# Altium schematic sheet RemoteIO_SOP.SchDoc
size 431 x 279 mm; Date: Not shown in title block; ApprovedBy: Not shown in title block; CheckedBy: Not shown in title block; Author: Not shown in title block; CompanyName: Not shown in title block; Engineer: Not shown in title block; Organization: Not shown in title block; Address1: Not shown in title block; Address2: Not shown in title block; Address3: Not shown in title block; Address4: Not shown in title block; DocumentNumber: 8; Revision: Use project parameter SCH_Rev; SheetNumber: 8; SheetTotal: 14; PageSetup: Record=PageOptions¦CenterHorizontal=True¦CenterVertical=True¦PrintScale=1.00¦XCorrection=1.00¦YCorrection=1.00¦PrintKind=0¦BorderSize=5000000¦LeftOffset=0¦BottomOffset=0¦Orientation=2¦PaperLength=1000¦PaperWidth=1000¦Scale=100¦PaperSource=15¦PrintQuality=600¦MediaType=1¦DitherType=10¦PaperKind=Letter¦PrintScaleMode=1
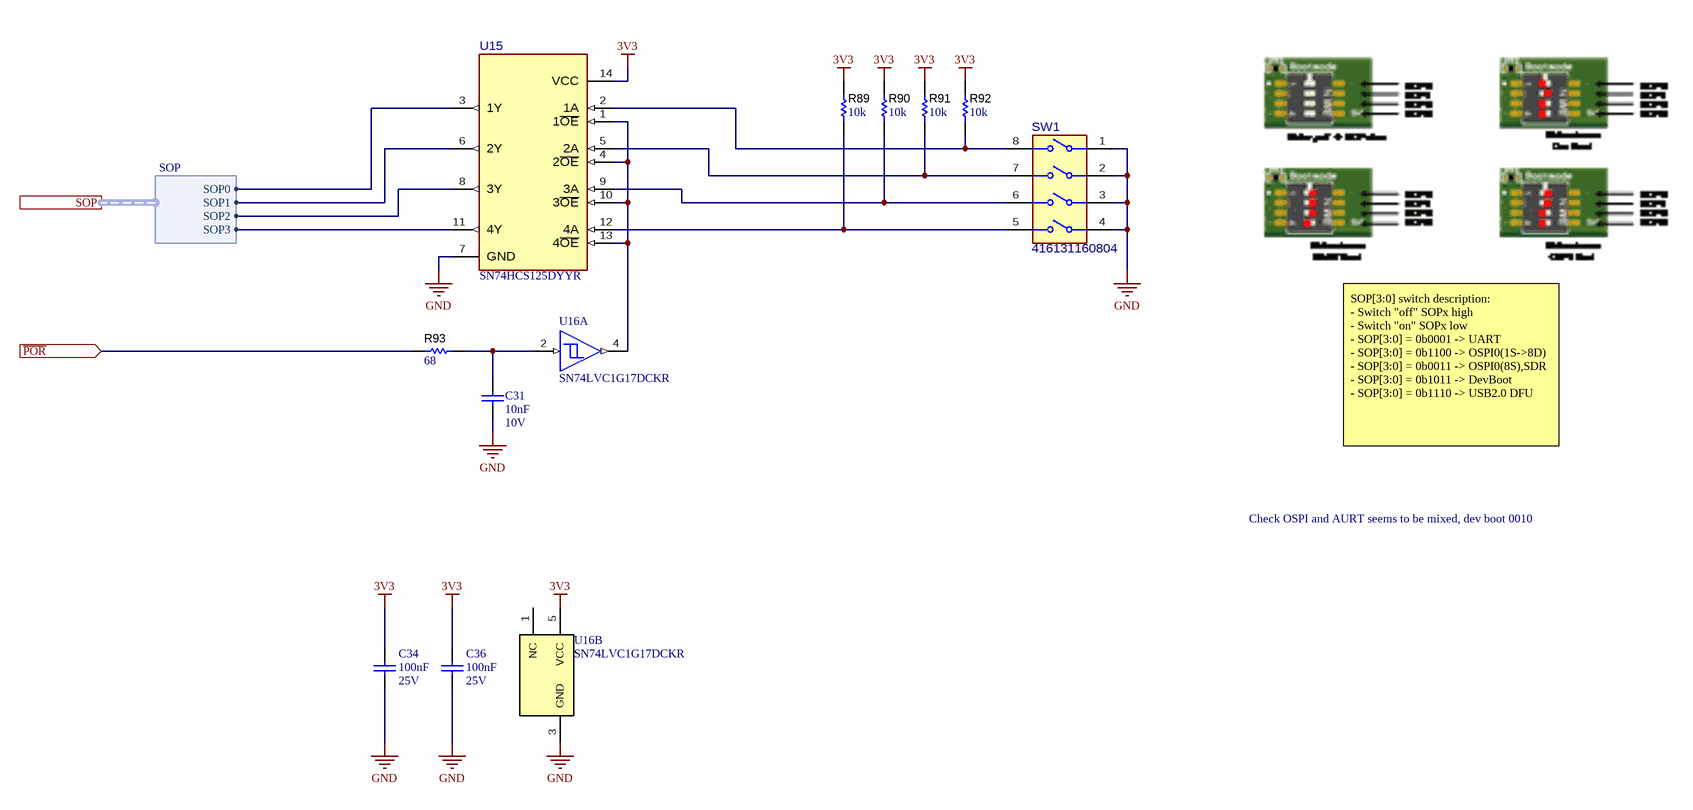
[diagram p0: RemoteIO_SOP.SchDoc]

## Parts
C31  Cap_F: 10nF  Rated Voltage (DC): 10V  [WCAP-CSGP_0402_L1W0.5H0.5]  (hidden comment: 885012205012)
C34  Cap_F: 100nF  Rated Voltage (DC): 25V  [WCAP-CSGP_0402_L1W0.5H0.5]  (hidden comment: 885012105018)
C36  Cap_F: 100nF  Rated Voltage (DC): 25V  [WCAP-CSGP_0402_L1W0.5H0.5]  (hidden comment: 885012105018)
R89  ValueDisplayed: 10k  [0402]  (hidden comment: CRCW040210K0JNED)
R90  ValueDisplayed: 10k  [0402]  (hidden comment: CRCW040210K0JNED)
R91  ValueDisplayed: 10k  [0402]  (hidden comment: CRCW040210K0JNED)
R92  ValueDisplayed: 10k  [0402]  (hidden comment: CRCW040210K0JNED)
R93  ValueDisplayed: 68  [0402]  (hidden comment: CRCW040268R0JNED)
SW1  416131160804  [FP-416131160804_SMT_SW-MFG]
U15  SN74HCS125DYYR  [DYY0014A-MFG]
U16  SN74LVC1G17DCKR  [DCK0005A_N]  (parts A,B of 2)

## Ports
SOP (harness SOP), ~{POR} (in)

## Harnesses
SOP: SOP0, SOP1, SOP2, SOP3

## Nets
3V3: C34.2 C36.2 R89.2 R90.2 R91.2 R92.2 U15.14(VCC) U16.5(VCC)
GND: C31.1 C34.1 C36.1 SW1.1 SW1.2 SW1.3 SW1.4 U15.7(GND) U16.3(GND)
~{POR}: R93.1 ; port ~{POR}
NetC31_2: C31.2 R93.2 U16.2(A)
NetR89_1: R89.1 SW1.5 U15.12(4A)
NetR90_1: R90.1 SW1.6 U15.9(3A)
NetR91_1: R91.1 SW1.7 U15.5(2A)
NetR92_1: R92.1 SW1.8 U15.2(1A)
NetU15_1: U15.1(1~{OE}) U15.4(2~{OE}) U15.10(3~{OE}) U15.13(4~{OE}) U16.4(Y)
NetU15_3: U15.3(1Y) ; port SOP.SOP0
NetU15_6: U15.6(2Y) ; port SOP.SOP1
NetU15_8: U15.8(3Y) ; port SOP.SOP2
NetU15_11: U15.11(4Y) ; port SOP.SOP3

Not connected (* = marked no-connect by the designer): U16 1(NC)

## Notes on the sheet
- SOP[3:0] switch description:
  - Switch "off" SOPx high
  - Switch "on" SOPx low
  - SOP[3:0] = 0b0001 -> UART                       - SOP[3:0] = 0b1100 -> OSPI0(1S->8D)                                  - SOP[3:0] = 0b0011 -> OSPI0(8S),SDR                       - SOP[3:0] = 0b1011 -> DevBoot
  - SOP[3:0] = 0b1110 -> USB2.0 DFU
- Check OSPI and AURT seems to be mixed, dev boot 0010

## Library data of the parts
C31 = CMP-0119242-1: WCAP-CSGP Multilayer Ceramic Chip Capacitor, General Purpose, size 0402, X7R, 10nF, 10VDC; Manufacturer: Wurth Elektronik; Capacitance Tolerance: +/-10%; Case/Size Code: 0402; Dissipation Factor: 5%; Insulation Resistance: 10GOhm; Technical Reference: X7R0402103K010DFCT10000
C34 C36 = CMP-0119143-1: WCAP-CSGP Multilayer Ceramic Chip Capacitor, General Purpose, size 0402, X5R, 100nF, 25VDC; Manufacturer: Wurth Elektronik; PartNumber: '885012105018; Capacitance Tolerance: +/-20%; Case/Size Code: 0402; Dissipation Factor: 10%; Insulation Resistance: 5GOhm; Technical Reference: X5R0402104M025DFCT10000
R89-R92 = CMP-0026825-5: RES, 10 k, 5%, 0.063 W, AEC-Q200 Grade 0, 0402; Manufacturer: Vishay-Dale; Power_W: 63mW; TempCo: 200 ppm/C; Value_Code: 10k0; Value: 10k; EIA_Code: E24; SizeX_mm: 1; SizeY_mm: 0.5; SizeZ_mm: 0.6; Value2: 0.063W; AEC Qualified: Y; VDC_V: 50V; AEC Category: Q200; AEC Grade: 0
R93 = CMP-0026964-3: RES, 68, 5%, 0.063 W, AEC-Q200 Grade 0, 0402; Manufacturer: Vishay-Dale; Power_W: 63mW; TempCo: 200 ppm/C; Value_Code: 68R0; Value: 68; EIA_Code: E24; SizeX_mm: 1; SizeY_mm: 0.5; SizeZ_mm: 0.6; Value2: 0.063W; AEC Qualified: Y; VDC_V: 50V; AEC Category: Q200; AEC Grade: 0
SW1 = CMP-0093176-1: Dip Switch SPST 4 Position Surface Mount Slide (Standard) Actuator 25mA 24VDC; Manufacturer: Wurth; PositionCount: 4; Electromechanical Life: 1000Cycles; Circuit: 4PST; Coil Resistance_ohm: 100mΩ; VDC_V: 24V; Standoff Height: 0mm; SizeZ_mm: 2.65mm; AEC Qualified: No
U15 = CMP-0127143-1: Schmitt-trigger inputs quadruple bus buffer gates with 3-state outputs 14-SOT-23-THIN -40 to 125; Manufacturer: Texas Instruments; SizeZ_mm: 1.1mm; AEC Qualified: No; Logic Function Desc: Non-Inverting; Max Supply Voltage: 6V; Min Supply Voltage: 2V; Nominal Supply Current: 0.1uA; Number Of Inputs: 4; PositionCount: 1; Propagation Delay: 5ns; Standoff Height: 0mm; TaMax_C: +125°C; TaMin_C: -40°C; TJmax_C: +150°C
U16 = CMP-0051704-3: Single Schmitt-Trigger Buffer, DCK0005A, LARGE T&R; Manufacturer: Texas Instruments; tpd @ Nom Voltage(Max)(ns): 11,6.5,5.5,5; Bits(#): 1; VCC(Min)(V): 1.65; F @ Nom Voltage(Max)(Mhz): 150; VCC(Max)(V): 5.5; Input Type: CMOS/TTL; Sub-Family: Non-Inverting Buffer/Driver; Output Type: CMOS; Output Drive (IOL/IOH)(Max)(mA): 32/-32; 3-State Output: No; Logic: True; ICC @ Nom Voltage(Max)(mA): 0.01; Voltage(Nom)(V): 1.8,2.5,3.3,5; Rating: Catalog; Schmitt Trigger: Yes; Technology Family: LVC; AEC Category: Q200; AEC Qualified: N; CompType: IC; SizeAreaWB_mm2: 9.3; SizeArea_mm2: 4.2; SizeX_mm: 2.1; SizeY_mm: 2.0; SizeZ_mm: 1.1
